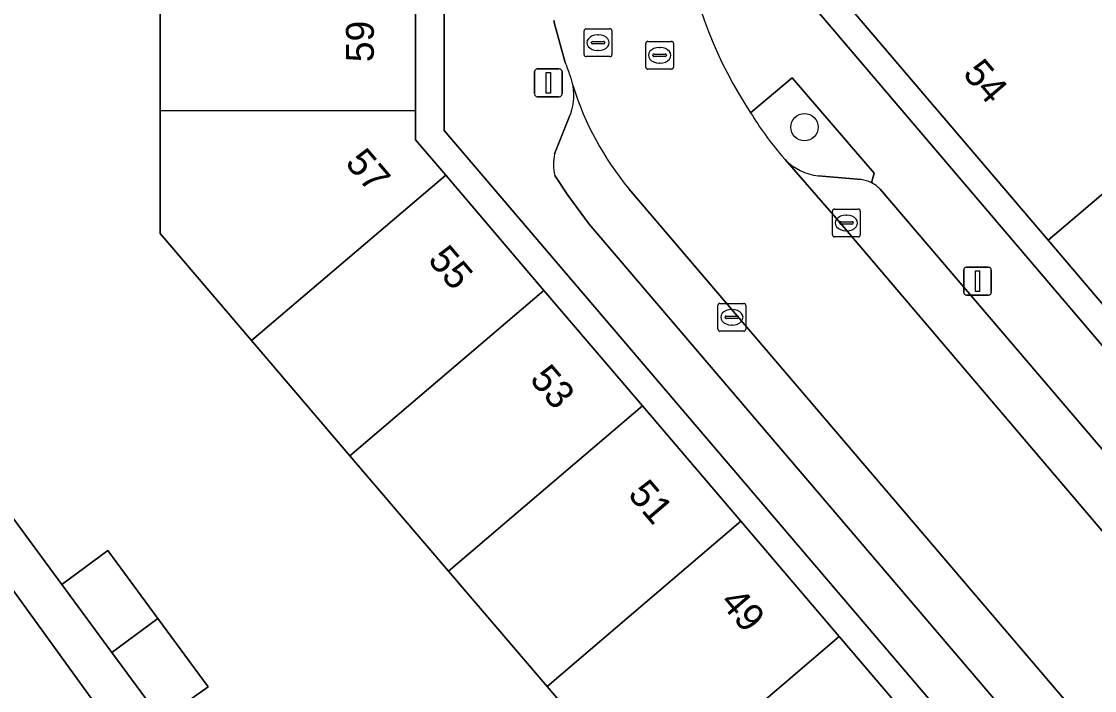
# Model space of a CAD drawing. Extents: x 160377 to 161131, y 383938 to 384853.
# Drawn here: x 160471.84 to 160510.39, y 384656.34 to 384680.38 of the extents above; entities that cross this region are included whole.
import ezdxf

# ---------------------------------------------------------------- set-up
doc = ezdxf.new("R2010")
doc.units = 0
for name, color, linetype in [('IMGEO_Boom', 7, 'Continuous'), ('IMGEO_Erf', 7, 'Continuous'), ('IMGEO_Groenvoorziening', 7, 'Continuous'), ('IMGEO_Kolk', 7, 'Continuous'), ('IMGEO_Lichtmast', 7, 'Continuous'), ('IMGEO_Pand', 7, 'Continuous'), ('IMGEO_Pand_nummerreeks', 7, 'Continuous'), ('IMGEO_Parkeervlak_open', 7, 'Continuous'), ('IMGEO_Rijbaan_lokaal_open', 7, 'Continuous'), ('IMGEO_Rioolput', 7, 'Continuous'), ('IMGEO_Voetpad_open', 7, 'Continuous')]:
    doc.layers.add(name, color=color, linetype=linetype)

msp = doc.modelspace()

# ---------------------------------------------------------------- linework, layer by layer
at = {"layer": 'IMGEO_Boom'}
msp.add_circle((160499.972, 384676.583), 0.489, dxfattribs=at)
at = {"layer": 'IMGEO_Erf'}
for points in [[(160603.494, 384626.95), (160531.839, 384722.221), (160517.199, 384711.18), (160499.817, 384698.107), (160499.831, 384681.477), (160544.574, 384628.905), (160558.691, 384612.377)], [(160524.356, 384632.684), (160487.022, 384676.465), (160487, 384704.676)], [(160555.646, 384617.452), (160552.287, 384621.39), (160548.74, 384625.548), (160545.194, 384629.706), (160541.647, 384633.863), (160538.1, 384638.021), (160534.556, 384642.176), (160533.571, 384643.324), (160530.017, 384647.502), (160526.468, 384651.672), (160522.92, 384655.843), (160519.371, 384660.013), (160515.823, 384664.184), (160512.275, 384668.354), (160508.724, 384672.527), (160500.837, 384681.797), (160500.846, 384687.066), (160500.855, 384692.343), (160500.864, 384697.632), (160510.089, 384704.569)], [(160486.009, 384698.761), (160486.006, 384693.362), (160486.004, 384687.962), (160486.001, 384682.563), (160485.998, 384677.164), (160485.998, 384676.129), (160487.085, 384674.855), (160490.612, 384670.719), (160494.149, 384666.573), (160497.685, 384662.426), (160501.222, 384658.279), (160504.77, 384654.119), (160497.8, 384648.191), (160494.261, 384652.336), (160490.722, 384656.481), (160487.183, 384660.625), (160483.644, 384664.77), (160480.106, 384668.915), (160476.825, 384672.757), (160476.825, 384677.176), (160476.826, 384682.568), (160476.826, 384687.967), (160476.826, 384693.366), (160476.827, 384698.765)], [(160466.274, 384669.689), (160473.289, 384660.154), (160474.942, 384661.376), (160476.747, 384658.927), (160478.552, 384656.477), (160476.868, 384655.289)], [(160476.868, 384655.289), (160475.09, 384657.706), (160473.289, 384660.154), (160466.274, 384669.689)], [(160464.883, 384669.131), (160479.261, 384649.275)]]:
    msp.add_lwpolyline(points, dxfattribs=at)
msp.add_lwpolyline([(160482.03, 384633.785), (160487.376, 384638.462), (160479.261, 384649.275), (160464.883, 384669.131), (160461.726, 384667.191)], close=True, dxfattribs=at)
at = {"layer": 'IMGEO_Groenvoorziening'}
for points in [[(160502.376, 384674.588), (160502.475, 384674.925), (160499.528, 384678.355), (160498.036, 384677.101)], [(160499.155, 384675.557), (160499.276, 384675.419)], [(160500.462, 384674.837), (160502.006, 384674.699)]]:
    msp.add_lwpolyline(points, dxfattribs=at)
for centre, radius, start, end in [((160508.488, 384683.498), 12.254, 211.4701, 220.3947), ((160500.668, 384676.756), 1.93, 223.8471, 263.8762), ((160501.883, 384673.615), 1.091, 63.0989, 83.5026)]:
    msp.add_arc(centre, radius, start, end, dxfattribs=at)
at = {"layer": 'IMGEO_Kolk'}
for p, q in [((160500.976, 384672.716), (160500.976, 384673.568)), ((160501.051, 384673.642), (160501.903, 384673.642)), ((160501.464, 384673.422), (160501.489, 384673.422)), ((160501.977, 384673.568), (160501.977, 384672.716)), ((160501.235, 384673.136), (160501.235, 384673.148)), ((160501.673, 384673.099), (160501.275, 384673.099)), ((160501.278, 384673.185), (160501.676, 384673.185)), ((160501.719, 384673.148), (160501.719, 384673.136)), ((160501.903, 384672.642), (160501.051, 384672.642)), ((160501.487, 384672.862), (160501.462, 384672.862)), ((160496.861, 384669.327), (160496.861, 384670.179)), ((160496.936, 384670.253), (160497.788, 384670.253)), ((160497.349, 384670.033), (160497.374, 384670.033)), ((160497.862, 384670.179), (160497.862, 384669.327)), ((160497.12, 384669.747), (160497.12, 384669.759)), ((160497.558, 384669.71), (160497.16, 384669.71)), ((160497.163, 384669.796), (160497.561, 384669.796)), ((160497.604, 384669.759), (160497.604, 384669.747)), ((160497.788, 384669.253), (160496.936, 384669.253)), ((160497.372, 384669.473), (160497.347, 384669.473))]:
    msp.add_line(p, q, dxfattribs=at)
for points in [[(160500.976, 384672.716), (160500.976, 384673.568)], [(160501.051, 384673.642), (160501.903, 384673.642)], [(160501.977, 384673.568), (160501.977, 384672.716)], [(160501.903, 384672.642), (160501.051, 384672.642)], [(160496.861, 384669.327), (160496.861, 384670.179)], [(160496.936, 384670.253), (160497.788, 384670.253)], [(160497.862, 384670.179), (160497.862, 384669.327)], [(160497.788, 384669.253), (160496.936, 384669.253)]]:
    msp.add_lwpolyline(points, dxfattribs=at)
for centre, radius, start, end in [((160501.053, 384673.566), 0.0765, 91.552, 178.448), ((160501.053, 384673.566), 0.0765, 91.552, 178.448), ((160501.901, 384673.566), 0.0765, 1.552, 88.448), ((160501.901, 384673.566), 0.0765, 1.552, 88.448), ((160501.275, 384673.145), 0.0403, 85.8775, 175.7526), ((160501.272, 384673.135), 0.0366, 178.938, 274.7102), ((160501.676, 384673.142), 0.043, 264.8664, 352.4533), ((160501.68, 384673.147), 0.0386, 1.7309, 96.639), ((160501.053, 384672.718), 0.0765, 181.552, 268.448), ((160501.053, 384672.718), 0.0765, 181.552, 268.448), ((160501.901, 384672.718), 0.0765, 271.552, 358.448), ((160501.901, 384672.718), 0.0765, 271.552, 358.448), ((160496.938, 384670.177), 0.0765, 91.552, 178.448), ((160496.938, 384670.177), 0.0765, 91.552, 178.448), ((160497.786, 384670.177), 0.0765, 1.552, 88.448), ((160497.786, 384670.177), 0.0765, 1.552, 88.448), ((160497.16, 384669.756), 0.0403, 85.8775, 175.7526), ((160497.157, 384669.746), 0.0366, 178.938, 274.7102), ((160497.561, 384669.753), 0.043, 264.8664, 352.4533), ((160497.565, 384669.758), 0.0386, 1.7309, 96.639), ((160496.938, 384669.329), 0.0765, 181.552, 268.448), ((160496.938, 384669.329), 0.0765, 181.552, 268.448), ((160497.786, 384669.329), 0.0765, 271.552, 358.448), ((160497.786, 384669.329), 0.0765, 271.552, 358.448)]:
    msp.add_arc(centre, radius, start, end, dxfattribs=at)
for centre, major_axis, ratio, start_param, end_param in [((160501.463, 384673.142), (-0.387, 0.002), 0.722429, 4.712389, 7.853982), ((160501.488, 384673.142), (-0.39, 0.002), 0.717154, 1.570796, 4.712389), ((160497.348, 384669.753), (-0.387, 0.002), 0.722429, 4.712389, 7.853982), ((160497.373, 384669.753), (-0.39, 0.002), 0.717154, 1.570796, 4.712389)]:
    msp.add_ellipse(centre, major_axis=major_axis, ratio=ratio, start_param=start_param, end_param=end_param, dxfattribs=at)
at = {"layer": 'IMGEO_Lichtmast'}
for p, q in [((160490.274, 384677.777), (160490.274, 384678.577)), ((160490.274, 384678.577), (160490.274, 384677.777)), ((160490.374, 384678.677), (160491.164, 384678.677)), ((160491.164, 384678.677), (160490.374, 384678.677)), ((160491.264, 384678.577), (160491.264, 384677.777)), ((160491.264, 384677.777), (160491.264, 384678.577)), ((160491.164, 384677.677), (160490.374, 384677.677)), ((160490.374, 384677.677), (160491.164, 384677.677)), ((160505.792, 384671.55), (160506.582, 384671.55)), ((160506.582, 384671.55), (160505.792, 384671.55)), ((160505.692, 384670.65), (160505.692, 384671.45)), ((160505.692, 384671.45), (160505.692, 384670.65)), ((160506.682, 384671.45), (160506.682, 384670.65)), ((160506.682, 384670.65), (160506.682, 384671.45)), ((160506.582, 384670.55), (160505.792, 384670.55)), ((160505.792, 384670.55), (160506.582, 384670.55))]:
    msp.add_line(p, q, dxfattribs=at)
for points in [[(160490.694, 384678.552), (160490.844, 384678.552), (160490.844, 384677.802), (160490.694, 384677.802), (160490.694, 384678.552)], [(160506.112, 384671.425), (160506.262, 384671.425), (160506.262, 384670.675), (160506.112, 384670.675), (160506.112, 384671.425)]]:
    msp.add_lwpolyline(points, dxfattribs=at)
for centre, start, end in [((160490.374, 384678.577), 90, 180), ((160490.374, 384678.577), 90, 180), ((160491.164, 384678.577), 0, 90), ((160491.164, 384678.577), 360, 90), ((160490.374, 384677.777), 180, 270), ((160490.374, 384677.777), 180, 270), ((160491.164, 384677.777), 270, 0), ((160491.164, 384677.777), 270, 0), ((160505.792, 384671.45), 90, 180), ((160505.792, 384671.45), 90, 180), ((160506.582, 384671.45), 0, 90), ((160506.582, 384671.45), 360, 90), ((160505.792, 384670.65), 180, 270), ((160505.792, 384670.65), 180, 270), ((160506.582, 384670.65), 270, 0), ((160506.582, 384670.65), 270, 0)]:
    msp.add_arc(centre, 0.1, start, end, dxfattribs=at)
at = {"layer": 'IMGEO_Pand'}
for points in [[(160486.001, 384682.563), (160476.826, 384682.568), (160476.825, 384677.176), (160485.998, 384677.164)], [(160513.001, 384678.269), (160509.999, 384681.781), (160500.837, 384681.797), (160508.724, 384672.527), (160514.045, 384677.042)], [(160519.266, 384674.291), (160515.722, 384678.465), (160514.045, 384677.042), (160508.724, 384672.527), (160512.275, 384668.354)], [(160487.085, 384674.855), (160485.998, 384676.129), (160485.998, 384677.164), (160476.825, 384677.176), (160476.825, 384672.757), (160480.106, 384668.915)], [(160490.612, 384670.719), (160487.085, 384674.855), (160480.106, 384668.915), (160483.644, 384664.77)], [(160494.149, 384666.573), (160490.612, 384670.719), (160483.644, 384664.77), (160487.183, 384660.625)], [(160497.685, 384662.426), (160494.149, 384666.573), (160487.183, 384660.625), (160490.722, 384656.481)], [(160501.222, 384658.279), (160497.685, 384662.426), (160490.722, 384656.481), (160494.261, 384652.336)], [(160474.942, 384661.376), (160473.289, 384660.154), (160475.09, 384657.706), (160476.747, 384658.927)], [(160476.747, 384658.927), (160475.09, 384657.706), (160476.868, 384655.289), (160478.552, 384656.477)], [(160504.77, 384654.119), (160501.222, 384658.279), (160494.261, 384652.336), (160497.8, 384648.191)]]:
    msp.add_lwpolyline(points, close=True, dxfattribs=at)
at = {"layer": 'IMGEO_Parkeervlak_open'}
for points in [[(160491.52, 384676.938), (160490.989, 384675.619)], [(160499.276, 384675.419), (160501.113, 384673.317), (160513.386, 384658.887)], [(160490.998, 384674.851), (160491.465, 384674.139), (160492.234, 384673.098), (160521.221, 384639.111)], [(160502.006, 384674.699), (160500.462, 384674.837)], [(160524.647, 384638.036), (160493.666, 384674.37)], [(160513.133, 384662.114), (160513.111, 384662.147), (160502.694, 384674.35)]]:
    msp.add_lwpolyline(points, dxfattribs=at)
for centre, radius, start, end in [((160489.793, 384677.72), 1.895, 335.646, 10.3179), ((160502.035, 384681.316), 10.876, 197.4275, 219.6933), ((160492.981, 384675.258), 2.024, 169.7344, 191.6084), ((160500.668, 384676.756), 1.93, 223.8471, 263.8762), ((160501.883, 384673.615), 1.091, 63.0989, 83.5026), ((160501.876, 384673.589), 1.117, 42.9448, 63.4308)]:
    msp.add_arc(centre, radius, start, end, dxfattribs=at)
at = {"layer": 'IMGEO_Rijbaan_lokaal_open'}
for points in [[(160490.968, 384680.419), (160490.976, 384680.376), (160490.983, 384680.347), (160491.378, 384678.909)], [(160513.386, 384658.887), (160501.113, 384673.317), (160499.276, 384675.419), (160499.155, 384675.557)], [(160493.666, 384674.37), (160524.647, 384638.036), (160525.3, 384637.294), (160529.002, 384640.499), (160528.953, 384640.556), (160513.957, 384658.216)]]:
    msp.add_lwpolyline(points, dxfattribs=at)
for centre, radius, start, end in [((160510.846, 384685.589), 15.367, 189.0148, 213.528), ((160502.089, 384682.502), 11.298, 198.544, 201.045), ((160505.081, 384682.198), 14.047, 195.4969, 197.1375), ((160502.035, 384681.316), 10.876, 197.4275, 219.6933), ((160508.488, 384683.498), 12.254, 211.4701, 220.3947)]:
    msp.add_arc(centre, radius, start, end, dxfattribs=at)
at = {"layer": 'IMGEO_Rioolput'}
for p, q in [((160492.055, 384679.191), (160492.055, 384680.043)), ((160492.13, 384680.117), (160492.982, 384680.117)), ((160493.056, 384680.043), (160493.056, 384679.191)), ((160492.314, 384679.611), (160492.314, 384679.623)), ((160492.357, 384679.66), (160492.755, 384679.66)), ((160492.543, 384679.897), (160492.568, 384679.897)), ((160492.798, 384679.623), (160492.798, 384679.611)), ((160494.268, 384678.74), (160494.268, 384679.592)), ((160494.343, 384679.666), (160495.195, 384679.666)), ((160495.269, 384679.592), (160495.269, 384678.74)), ((160492.752, 384679.574), (160492.354, 384679.574)), ((160492.566, 384679.337), (160492.541, 384679.337)), ((160494.57, 384679.209), (160494.968, 384679.209)), ((160494.756, 384679.446), (160494.781, 384679.446)), ((160492.982, 384679.117), (160492.13, 384679.117)), ((160494.527, 384679.16), (160494.527, 384679.172)), ((160494.965, 384679.123), (160494.567, 384679.123)), ((160494.779, 384678.886), (160494.754, 384678.886)), ((160495.011, 384679.172), (160495.011, 384679.16)), ((160495.195, 384678.666), (160494.343, 384678.666))]:
    msp.add_line(p, q, dxfattribs=at)
for points in [[(160492.055, 384679.191), (160492.055, 384680.043)], [(160492.13, 384680.117), (160492.982, 384680.117)], [(160493.056, 384680.043), (160493.056, 384679.191)], [(160494.268, 384678.74), (160494.268, 384679.592)], [(160494.343, 384679.666), (160495.195, 384679.666)], [(160495.269, 384679.592), (160495.269, 384678.74)], [(160492.982, 384679.117), (160492.13, 384679.117)], [(160495.195, 384678.666), (160494.343, 384678.666)]]:
    msp.add_lwpolyline(points, dxfattribs=at)
for centre, radius, start, end in [((160492.132, 384680.041), 0.0765, 91.552, 178.448), ((160492.132, 384680.041), 0.0765, 91.552, 178.448), ((160492.98, 384680.041), 0.0765, 1.552, 88.448), ((160492.98, 384680.041), 0.0765, 1.552, 88.448), ((160492.354, 384679.62), 0.0403, 85.8775, 175.7526), ((160492.351, 384679.61), 0.0366, 178.938, 274.7102), ((160492.755, 384679.617), 0.043, 264.8664, 352.4533), ((160492.759, 384679.622), 0.0386, 1.7309, 96.639), ((160494.345, 384679.59), 0.0765, 91.552, 178.448), ((160494.345, 384679.59), 0.0765, 91.552, 178.448), ((160495.193, 384679.59), 0.0765, 1.552, 88.448), ((160495.193, 384679.59), 0.0765, 1.552, 88.448), ((160492.132, 384679.193), 0.0765, 181.552, 268.448), ((160492.132, 384679.193), 0.0765, 181.552, 268.448), ((160492.98, 384679.193), 0.0765, 271.552, 358.448), ((160492.98, 384679.193), 0.0765, 271.552, 358.448), ((160494.567, 384679.169), 0.0403, 85.8775, 175.7526), ((160494.972, 384679.171), 0.0386, 1.7309, 96.639), ((160494.564, 384679.159), 0.0366, 178.938, 274.7102), ((160494.968, 384679.166), 0.043, 264.8664, 352.4533), ((160494.345, 384678.742), 0.0765, 181.552, 268.448), ((160494.345, 384678.742), 0.0765, 181.552, 268.448), ((160495.193, 384678.742), 0.0765, 271.552, 358.448), ((160495.193, 384678.742), 0.0765, 271.552, 358.448)]:
    msp.add_arc(centre, radius, start, end, dxfattribs=at)
for centre, major_axis, ratio, start_param, end_param in [((160492.542, 384679.617), (-0.387, 0.002), 0.722429, 4.712389, 7.853982), ((160492.567, 384679.617), (-0.39, 0.002), 0.717154, 1.570796, 4.712389), ((160494.755, 384679.166), (-0.387, 0.002), 0.722429, 4.712389, 7.853982), ((160494.78, 384679.166), (-0.39, 0.002), 0.717154, 1.570796, 4.712389)]:
    msp.add_ellipse(centre, major_axis=major_axis, ratio=ratio, start_param=start_param, end_param=end_param, dxfattribs=at)
at = {"layer": 'IMGEO_Voetpad_open'}
for points in [[(160525.346, 384728.904), (160525.467, 384728.995), (160526.24, 384729.625), (160524.022, 384732.549), (160523.198, 384731.929), (160487, 384704.676), (160487.022, 384676.465), (160524.356, 384632.684), (160526.662, 384629.966)], [(160610.459, 384499.743), (160614.226, 384500.488), (160611.199, 384533.452), (160609.42, 384552.826), (160588.469, 384577.392), (160578.674, 384588.862), (160577.214, 384590.588), (160574.938, 384593.252), (160571.697, 384597.097), (160570.15, 384598.933), (160561.787, 384608.701), (160558.691, 384612.377), (160544.574, 384628.905), (160499.831, 384681.477), (160499.817, 384698.107), (160517.199, 384711.18), (160531.839, 384722.221), (160534.832, 384724.029)], [(160491.378, 384678.909), (160490.983, 384680.347), (160490.976, 384680.376), (160490.968, 384680.419)], [(160498.036, 384677.101), (160499.528, 384678.355), (160502.475, 384674.925), (160502.376, 384674.588)], [(160490.989, 384675.619), (160491.52, 384676.938)], [(160526.047, 384636.403), (160525.902, 384636.576), (160524.378, 384635.261), (160521.123, 384639.026), (160521.221, 384639.111), (160492.234, 384673.098), (160491.465, 384674.139), (160490.998, 384674.851)], [(160502.694, 384674.35), (160513.111, 384662.147), (160513.133, 384662.114)]]:
    msp.add_lwpolyline(points, dxfattribs=at)
for centre, radius, start, end in [((160510.846, 384685.589), 15.367, 189.0148, 213.528), ((160502.089, 384682.502), 11.298, 198.544, 201.045), ((160505.081, 384682.198), 14.047, 195.4969, 197.1375), ((160489.793, 384677.72), 1.895, 335.646, 10.3179), ((160492.981, 384675.258), 2.024, 169.7344, 191.6084), ((160501.876, 384673.589), 1.117, 42.9448, 63.4308)]:
    msp.add_arc(centre, radius, start, end, dxfattribs=at)

# ---------------------------------------------------------------- texts
at = {"layer": 'IMGEO_Pand_nummerreeks'}
for s, rotation, p in [('59', 89.9716, (160484.5, 384678.917)), ('54', 310.3933, (160505.624, 384678.486)), ('57', 310.4621, (160483.439, 384675.277)), ('55', 310.4621, (160486.41, 384671.794)), ('53', 310.4621, (160490.066, 384667.508)), ('51', 310.4621, (160493.595, 384663.37)), ('49', 310.4621, (160496.901, 384659.493))]:
    msp.add_text(s, height=1, rotation=rotation, dxfattribs=at).set_placement(p)

doc.saveas('drawing.dxf')
